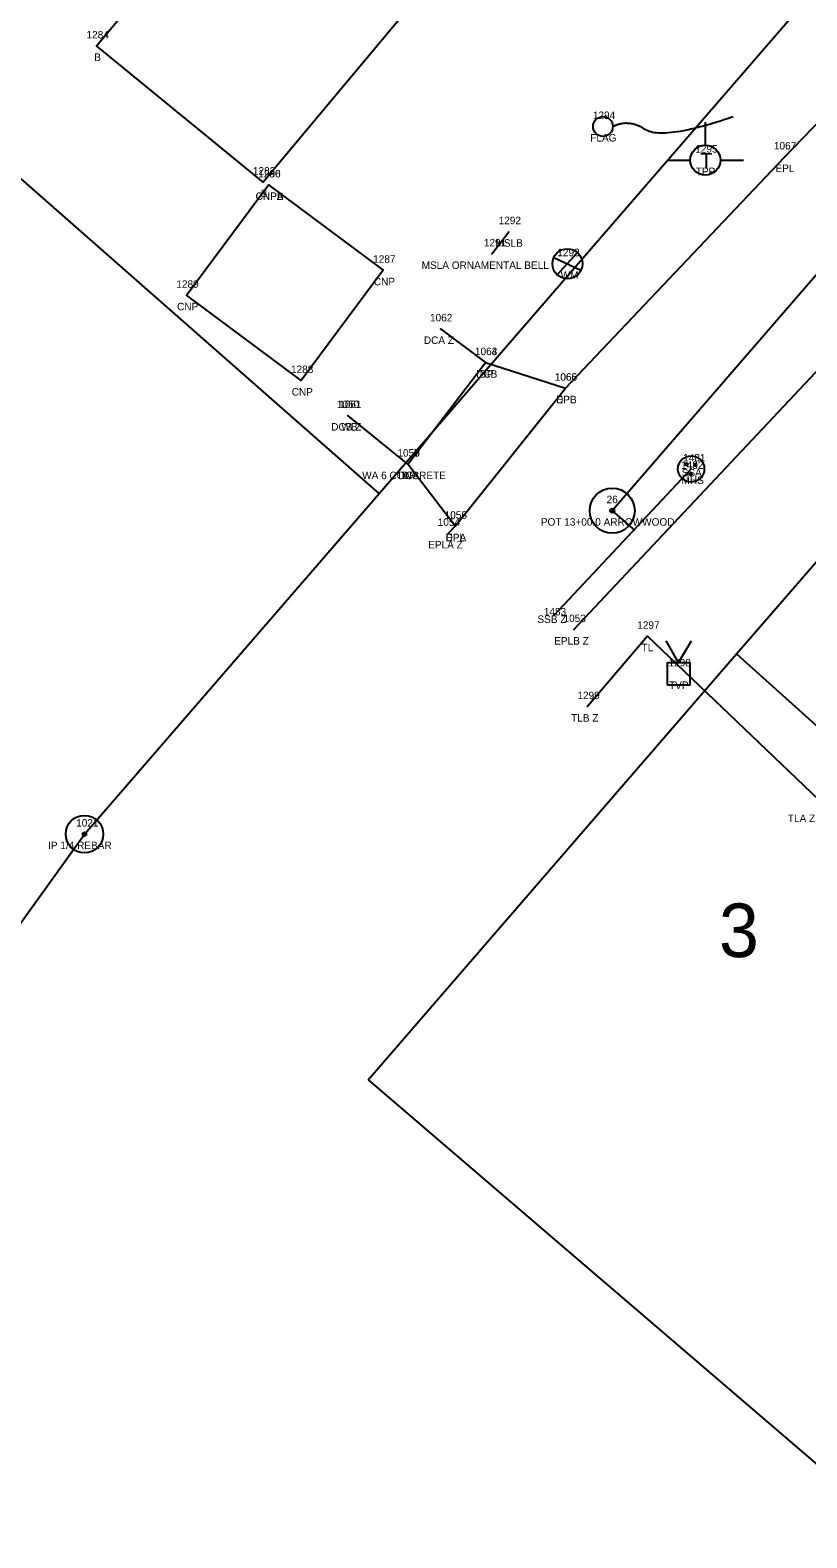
# Model space of a CAD drawing. Extents: x 1812113 to 1819860, y 1177395 to 1181185.
# Drawn here: x 1813774.2 to 1813877.7, y 1178074.8 to 1178275.6 of the extents above; entities that cross this region are included whole.
import ezdxf

# ---------------------------------------------------------------- set-up
doc = ezdxf.new("R2010")
doc.units = 0
for name, color, linetype in [('RD_EX_Bldg', 7, 'Continuous'), ('RD_EX_Bldg_txCode', 7, 'Continuous'), ('RD_EX_BldgApp', 7, 'Continuous'), ('RD_EX_BldgApp_txCode', 7, 'Continuous'), ('RD_EX_Conc', 7, 'Continuous'), ('RD_EX_Conc_txCode', 7, 'Continuous'), ('RD_EX_DR_Inlet', 7, 'Continuous'), ('RD_EX_Driveway', 7, 'Continuous'), ('RD_EX_Driveway_txCode', 7, 'Continuous'), ('RD_EX_DV_Prop', 7, 'Continuous'), ('RD_EX_DV_Prop_txCode', 7, 'Continuous'), ('RD_EX_DV_PropPin', 7, 'Continuous'), ('RD_EX_DV_TX_Prop', 7, 'Continuous'), ('RD_EX_Misc', 7, 'Continuous'), ('RD_EX_Misc_txCode', 7, 'Continuous'), ('RD_EX_Road', 7, 'Continuous'), ('RD_EX_Road_txCode', 7, 'Continuous'), ('RD_EX_SU_Telecom', 7, 'Continuous'), ('RD_EX_UT', 7, 'Continuous'), ('RD_EX_UT_txCode', 7, 'Continuous'), ('RD_EX_VEG', 7, 'Continuous'), ('RD_EX_VEG_txCode', 7, 'Continuous'), ('RD_HC_CL', 7, 'Continuous'), ('RD_HC_Data', 7, 'Continuous'), ('RD_HC_Data_Tic', 7, 'Continuous'), ('RD_HC_txCode', 7, 'Continuous'), ('RD_SMD_Locator', 7, 'Continuous')]:
    doc.layers.add(name, color=color, linetype=linetype)

msp = doc.modelspace()

# ---------------------------------------------------------------- linework, layer by layer
at = {"layer": 'RD_EX_Bldg'}
msp.add_lwpolyline([(1813814.41, 1178311.05), (1813836.59, 1178292.91), (1813805.22, 1178255.39), (1813783.05, 1178273.53), (1813814.41, 1178311.05)], dxfattribs=at)
at = {"layer": 'RD_EX_BldgApp'}
msp.add_line((1813824.51, 1178217.83), (1813816.5, 1178224.3), dxfattribs=at)
msp.add_lwpolyline([(1813805.96, 1178255.02), (1813821.24, 1178243.65), (1813810.29, 1178228.96), (1813795.02, 1178240.32), (1813805.96, 1178255.02)], dxfattribs=at)
at = {"layer": 'RD_EX_Conc'}
for p, q in [((1813828.87, 1178235.84), (1813834.86, 1178231.35)), ((1813824.51, 1178217.83), (1813816.5, 1178224.3))]:
    msp.add_line(p, q, dxfattribs=at)
at = {"layer": 'RD_EX_DR_Inlet'}
for centre, radius in [((1813862.25, 1178217.19), 1.75), ((1813861.59, 1178217.82), 0.175), ((1813862.17, 1178216.52), 0.175), ((1813862.81, 1178217.75), 0.175)]:
    msp.add_circle(centre, radius, dxfattribs=at)
at = {"layer": 'RD_EX_Driveway'}
msp.add_lwpolyline([(1813830.81, 1178209.56), (1813824.51, 1178217.83), (1813834.86, 1178231.35), (1813845.51, 1178227.94)], dxfattribs=at)
at = {"layer": 'RD_EX_DV_Prop'}
for p, q in [((1813820.68, 1178213.93), (1813702.17, 1178317.99)), ((1813820.68, 1178213.93), (1813876.31, 1178278.23)), ((1813868.31, 1178192.56), (1813914.12, 1178245.52)), ((1813781.43, 1178168.55), (1813820.68, 1178213.93)), ((1813819.24, 1178135.84), (1813868.31, 1178192.56)), ((1813868.31, 1178192.56), (1814033.95, 1178043.26)), ((1813768.12, 1178150.07), (1813781.43, 1178168.55)), ((1813819.24, 1178135.84), (1813982.43, 1177995.87))]:
    msp.add_line(p, q, dxfattribs=at)
at = {"layer": 'RD_EX_DV_PropPin'}
for radius in [2.5, 0.25]:
    msp.add_circle((1813781.43, 1178168.55), radius, dxfattribs=at)
at = {"layer": 'RD_EX_Misc'}
msp.add_line((1813835.69, 1178245.83), (1813837.95, 1178248.79), dxfattribs=at)
at = {"layer": 'RD_EX_Road'}
for p, q in [((1813874.69, 1178258.74), (1813910.02, 1178295.38)), ((1813845.51, 1178227.94), (1813874.69, 1178258.74)), ((1813888.9, 1178240.78), (1813846.63, 1178195.79)), ((1813830.81, 1178209.56), (1813845.51, 1178227.94)), ((1813829.87, 1178208.6), (1813830.81, 1178209.56))]:
    msp.add_line(p, q, dxfattribs=at)
at = {"layer": 'RD_EX_SU_Telecom'}
msp.add_circle((1813850.5, 1178262.8), 1.32, dxfattribs=at)
msp.add_open_spline([(1813851.82, 1178262.8), (1813853.83, 1178263.9), (1813858.51, 1178260.95), (1813867.87, 1178264.13)], degree=2, dxfattribs=at)
at = {"layer": 'RD_EX_UT'}
for p, q in [((1813864.14, 1178263.39), (1813864.14, 1178260.32)), ((1813859.21, 1178258.34), (1813862.14, 1178258.34)), ((1813866.14, 1178258.34), (1813869.21, 1178258.34)), ((1813843.94, 1178245.36), (1813847.57, 1178243.65)), ((1813844.42, 1178243.06), (1813847.08, 1178245.96)), ((1813862.26, 1178217.2), (1813843.97, 1178197.68)), ((1813860.58, 1178191.39), (1813858.92, 1178194.28)), ((1813860.58, 1178191.39), (1813862.32, 1178194.28))]:
    msp.add_line(p, q, dxfattribs=at)
msp.add_lwpolyline([(1813859.08, 1178188.39), (1813859.08, 1178191.39), (1813862.08, 1178191.39), (1813862.08, 1178188.39)], close=True, dxfattribs=at)
for centre in [(1813864.14, 1178258.32), (1813845.77, 1178244.52)]:
    msp.add_circle(centre, 2, dxfattribs=at)
at = {"layer": 'RD_EX_VEG'}
msp.add_lwpolyline([(1813880.29, 1178172.15), (1813856.42, 1178194.9), (1813848.45, 1178185.53)], dxfattribs=at)
at = {"layer": 'RD_HC_CL'}
msp.add_line((1814048.02, 1178438.51), (1813851.74, 1178211.63), dxfattribs=at)
at = {"layer": 'RD_HC_Data'}
for radius in [3, 0.282]:
    msp.add_circle((1813851.74, 1178211.63), radius, dxfattribs=at)
at = {"layer": 'RD_HC_Data_Tic'}
msp.add_line((1813851.74, 1178211.63), (1813854.77, 1178209.01), dxfattribs=at)
at = {"layer": 'RD_SMD_Locator'}
for centre in [(1813783.05, 1178273.53), (1813874.69, 1178258.74), (1813805.22, 1178255.39), (1813805.96, 1178255.02), (1813805.96, 1178255.02), (1813837.95, 1178248.79), (1813835.69, 1178245.83), (1813821.24, 1178243.65), (1813795.02, 1178240.32), (1813828.87, 1178235.84), (1813834.86, 1178231.35), (1813834.86, 1178231.35), (1813810.29, 1178228.96), (1813845.51, 1178227.94), (1813845.51, 1178227.94), (1813816.5, 1178224.3), (1813816.5, 1178224.3), (1813824.51, 1178217.83), (1813824.51, 1178217.83), (1813824.51, 1178217.83), (1813862.26, 1178217.2), (1813851.74, 1178211.63), (1813829.87, 1178208.6), (1813830.81, 1178209.56), (1813830.81, 1178209.56), (1813843.97, 1178197.68), (1813846.63, 1178195.79), (1813856.42, 1178194.9), (1813848.45, 1178185.53)]:
    msp.add_circle(centre, 0.001, dxfattribs=at)

# ---------------------------------------------------------------- texts
at = {"layer": 'RD_EX_Bldg_txCode'}
for s, p in [('1284', (1813781.7, 1178274.53)), ('B', (1813782.74, 1178271.53)), ('1283', (1813803.87, 1178256.39)), ('B', (1813804.91, 1178253.39))]:
    msp.add_text(s, height=1, dxfattribs=at).set_placement(p)
at = {"layer": 'RD_EX_BldgApp_txCode'}
for s, p in [('1294', (1813849.16, 1178263.8)), ('FLAG', (1813848.81, 1178260.8)), ('1290', (1813804.58, 1178256.02)), ('1286', (1813804.59, 1178256.02)), ('CNPA', (1813804.22, 1178253.02)), ('CNPB', (1813804.24, 1178253.02)), ('1287', (1813819.89, 1178244.65)), ('1289', (1813793.67, 1178241.32)), ('CNP', (1813819.98, 1178241.65)), ('CNP', (1813793.77, 1178238.32)), ('1288', (1813808.94, 1178229.96)), ('CNP', (1813809.04, 1178226.96)), ('1060', (1813815.05, 1178225.3)), ('WB', (1813815.65, 1178222.3)), ('1059', (1813823.12, 1178218.83)), ('WA 6 CONCRETE', (1813818.43, 1178215.83))]:
    msp.add_text(s, height=1, dxfattribs=at).set_placement(p)
at = {"layer": 'RD_EX_Conc_txCode'}
for s, p in [('1062', (1813827.46, 1178236.84)), ('DCA Z', (1813826.64, 1178233.84)), ('1063', (1813833.45, 1178232.35)), ('DCB', (1813833.61, 1178229.35)), ('1061', (1813815.37, 1178225.3)), ('DCB Z', (1813814.3, 1178222.3)), ('1058', (1813823.12, 1178218.83)), ('DCA', (1813823.24, 1178215.83))]:
    msp.add_text(s, height=1, dxfattribs=at).set_placement(p)
at = {"layer": 'RD_EX_Driveway_txCode'}
for s, p in [('1064', (1813833.45, 1178232.35)), ('DP', (1813834.08, 1178229.35)), ('1065', (1813844.1, 1178228.94)), ('DPB', (1813844.26, 1178225.94)), ('1057', (1813823.12, 1178218.83)), ('DP', (1813823.73, 1178215.83)), ('1056', (1813829.4, 1178210.56)), ('DPA', (1813829.54, 1178207.56))]:
    msp.add_text(s, height=1, dxfattribs=at).set_placement(p)
at = {"layer": 'RD_EX_DV_Prop_txCode'}
for s, p in [('1021', (1813780.32, 1178169.55)), ('IP 1/4 REBAR', (1813776.58, 1178166.55))]:
    msp.add_text(s, height=1, dxfattribs=at).set_placement(p)
at = {"layer": 'RD_EX_DV_TX_Prop'}
msp.add_text('3', height=7.14, dxfattribs=at).set_placement((1813865.96, 1178152.17))
at = {"layer": 'RD_EX_Misc_txCode'}
for s, p in [('1292', (1813836.61, 1178249.79)), ('1291', (1813834.63, 1178246.83)), ('MSLB', (1813836.19, 1178246.79)), ('MSLA ORNAMENTAL BELL', (1813826.35, 1178243.83))]:
    msp.add_text(s, height=1, dxfattribs=at).set_placement(p)
at = {"layer": 'RD_EX_Road_txCode'}
for s, p in [('1067', (1813873.28, 1178259.74)), ('EPL', (1813873.48, 1178256.74)), ('1066', (1813844.07, 1178228.94)), ('EPL', (1813844.3, 1178225.94)), ('1054', (1813828.49, 1178209.6)), ('1055', (1813829.42, 1178210.56)), ('EPL', (1813829.6, 1178207.56)), ('EPLA Z', (1813827.22, 1178206.6)), ('1053', (1813845.25, 1178196.79)), ('EPLB Z', (1813844.01, 1178193.79))]:
    msp.add_text(s, height=1, dxfattribs=at).set_placement(p)
at = {"layer": 'RD_EX_UT'}
msp.add_text('T', height=2, dxfattribs=at).set_placement((1813863.47, 1178257.27))
at = {"layer": 'RD_EX_UT_txCode'}
for s, p in [('1295', (1813862.8, 1178259.32)), ('TPP', (1813862.87, 1178256.32)), ('1293', (1813844.42, 1178245.52)), ('WM', (1813844.86, 1178242.52)), ('1482', (1813860.91, 1178217.2)), ('1481', (1813861.19, 1178218.19)), ('SSA', (1813860.99, 1178216.2)), ('MHS', (1813860.96, 1178215.19)), ('1483', (1813842.62, 1178197.68)), ('SSB Z', (1813841.77, 1178196.68)), ('1298', (1813859.24, 1178190.89)), ('TVP', (1813859.3, 1178187.89))]:
    msp.add_text(s, height=1, dxfattribs=at).set_placement(p)
at = {"layer": 'RD_EX_VEG_txCode'}
for s, p in [('1297', (1813855.07, 1178195.9)), ('TL', (1813855.65, 1178192.9)), ('1299', (1813847.1, 1178186.53)), ('TLB Z', (1813846.26, 1178183.53)), ('TLA Z WOODS', (1813875.14, 1178170.15))]:
    msp.add_text(s, height=1, dxfattribs=at).set_placement(p)
at = {"layer": 'RD_HC_txCode'}
for s, p in [('26', (1813850.99, 1178212.63)), ('POT 13+00.0 ARROWWOOD', (1813842.23, 1178209.63))]:
    msp.add_text(s, height=1, dxfattribs=at).set_placement(p)

doc.saveas('drawing.dxf')
